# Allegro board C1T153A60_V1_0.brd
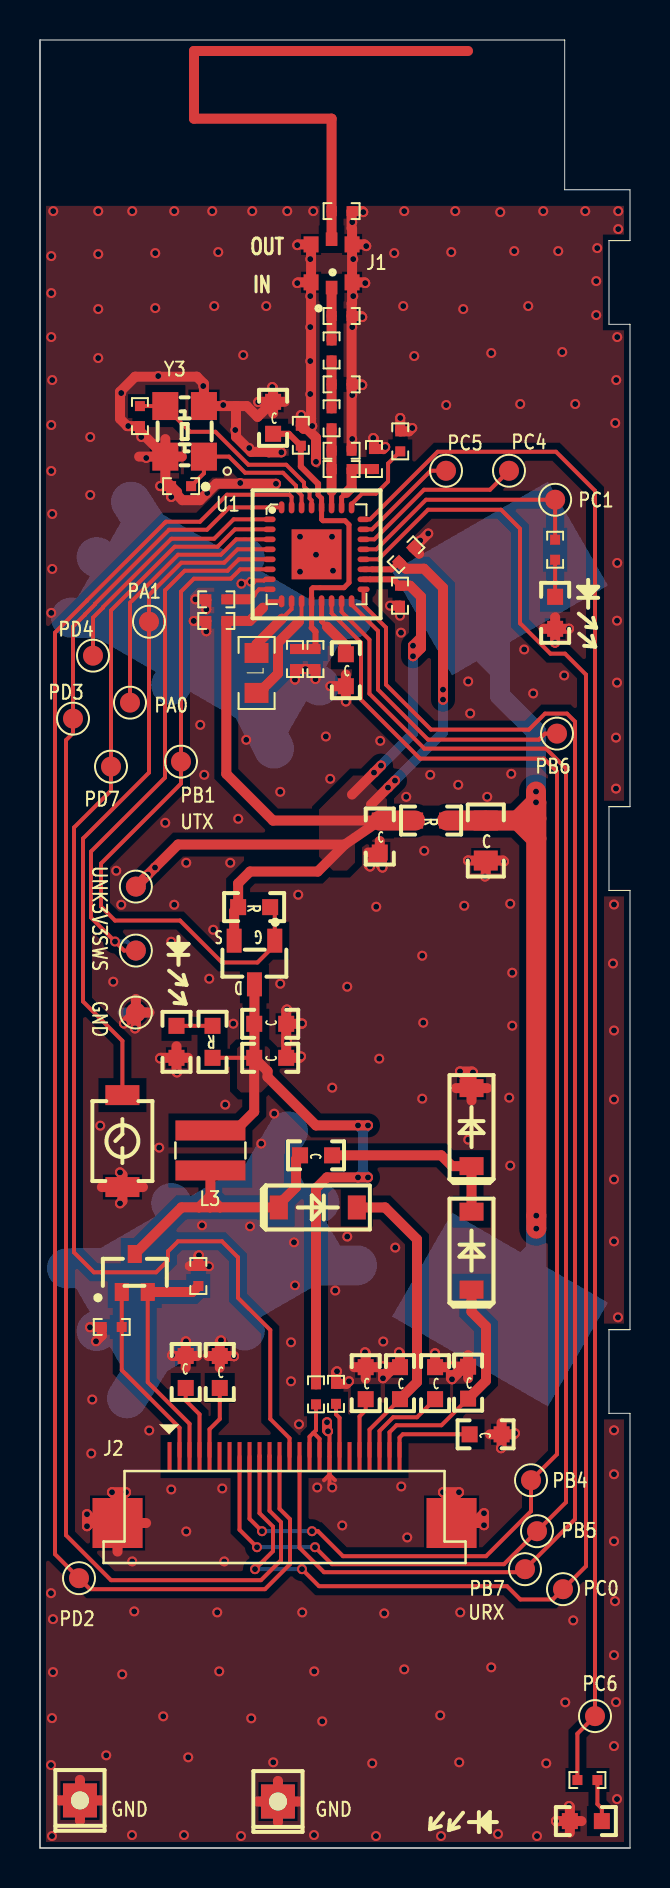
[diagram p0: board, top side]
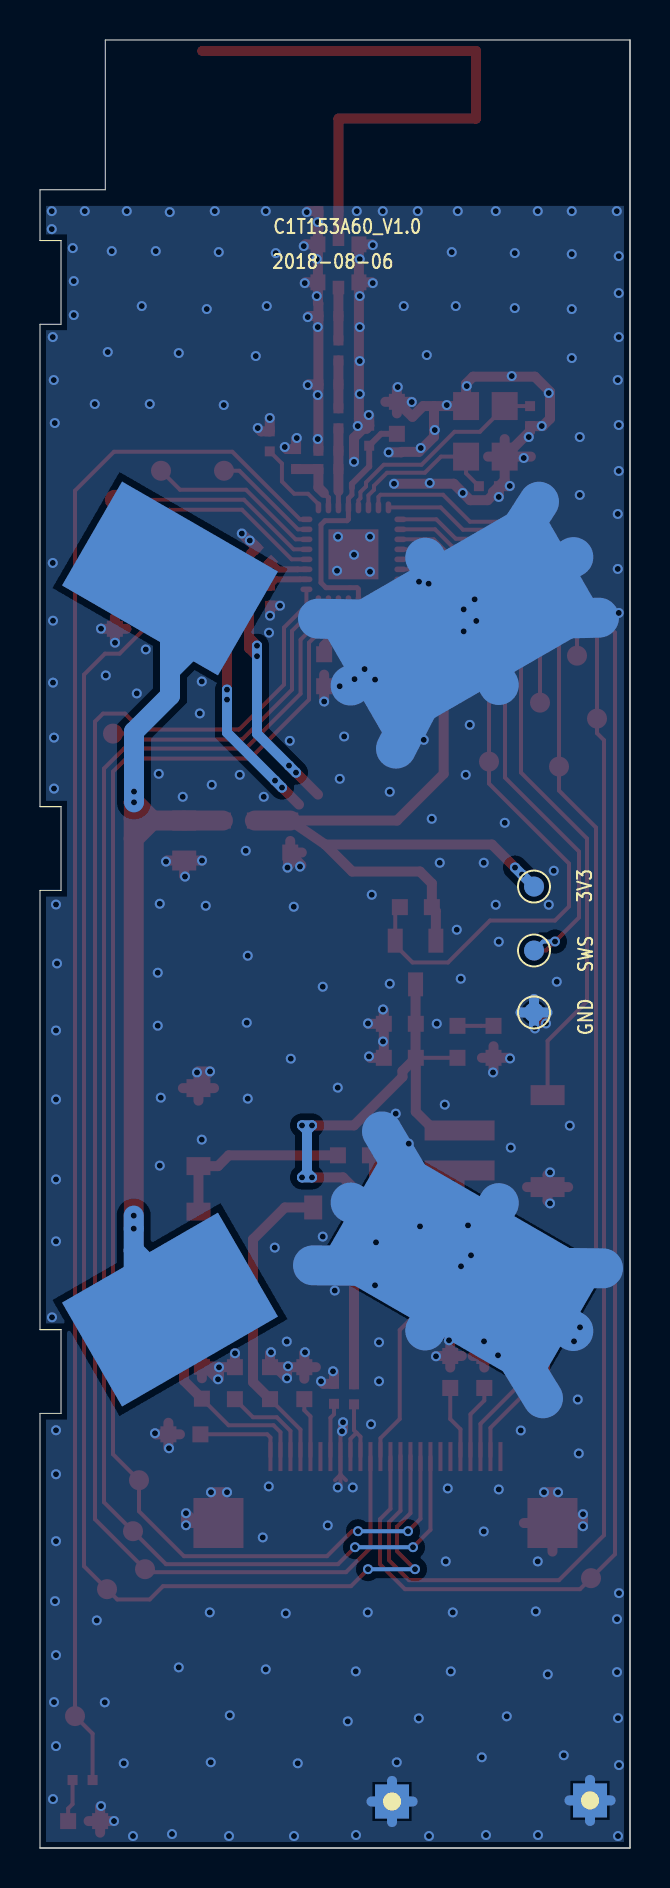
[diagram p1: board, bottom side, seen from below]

Outline 29.5 x 90.45 mm; copper layers: TOP, BOTTOM. Coordinates in mm from the lower left corner of the outline.
Outline path: 0,90.45 0,0 ; 0,90.45 26.23,90.45 26.23,82.96 29.5,82.96 29.5,80.42 ; 0,90.45 0,0 ; 0,0 29.5,0 ; 0,0 29.5,0 ; 29.5,0 29.5,21.74 28.45,21.74 28.45,25.93 ; 28.45,80.42 28.45,76.23 29.5,76.23 29.5,52.1 ; 28.45,80.42 29.5,80.42 ; 28.45,80.42 29.5,80.42 ; 28.45,52.1 28.45,47.9 29.5,47.9 29.5,25.93 ; 28.45,52.1 29.5,52.1 ; 28.45,52.1 29.5,52.1 ; 28.45,25.93 29.5,25.93 ; 28.45,25.93 29.5,25.93

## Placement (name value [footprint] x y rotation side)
BT3  3V  [BAT_P1]  8.4 29.08 90 bottom
C4  1.5pF  [0402]  15.08 73.22 0 top
C5  1.5pF  [0402]  15.08 76.64 0 top
C6  220pF  [0402]  14.58 71.52 90 top
C7  NC  [0402]  15.08 69.9 0 top
C8  1uF/25V  [0603C]  7.29 23.81 270 top
C9  1uF/25V  [0603C]  8.99 23.81 270 top
C10  1pF  [0402]  15.08 81.89 0 top
C13  1uF/25V  [0402]  14.8 22.72 270 top
C16  4.7uF/50V  [0603C]  13.8 34.65 180 top
C17  1uF/25V  [0603C]  19.75 23.25 270 top
C18  1uF/25V  [0603C]  16.28 23.25 270 top
C19  1uF/6V  [0603C]  22.28 20.7 180 top
C20  1uF/50V  [0603C]  18 23.26 270 top
C21  1uF/50V  [0603C]  21.4 23.28 270 top
C23  1uF  [0603C]  11.51 39.53 0 top
C24  10uF  [0603C]  11.51 41.23 0 top
C27  10uF  [0603C]  16.99 50.6 270 top
C28  10uF  [0805C]  22.29 50.4 270 top
C30  1uF  [0402]  18 62.65 270 top
C31  1uF  [0402]  8.82 61.39 180 top
C32  1uF  [0402]  8.82 62.47 0 top
C33  0.1uF  [0402]  13.77 59.48 270 top
C34  1uF  [0402]  18.01 70.37 90 top
C35  1uF  [0402]  12.75 59.48 270 top
C36  NC  [0402]  5 71.63 90 top
C37  NC  [0402]  7.05 68.13 0 top
C39  1uF  [0402]  18.3 64.7 45 top
C41  1uF  [0603C]  15.29 58.92 270 top
C42  18pF  [0402]  16.7 69.49 270 top
C43  0.1uF  [0402]  13.04 70.65 270 top
C44  2.2uF  [0603C]  11.65 71.55 270 top
D1  MBR0530  [SOD-123]  21.58 36.06 270 top
D2  MBR0530  [SOD-123]  13.89 32.04 180 top
D3  MBR0530  [SOD-123]  21.58 29.88 270 top
D4  Blue  [0603-LED]  6.82 40.33 270 top
D5  Green  [0603-LED]  27.29 1.35 180 top
D6  Red  [0603-LED]  25.76 61.79 270 top
GND  TP  [TP100]  4.79 41.8 90 top
J1  MM8130  [MM8130-2600]  14.58 79.27 180 top
J2  24FLZ-SM2-GD-TB  [FPC_24PIN]  12.23 19.58 0 top
J9  NC  [HDR254F-1X1X850]  2 2.38 90 top
J10  NC  [HDR254F-1X1X850]  11.9 2.33 90 top
L1  3nH  [0402]  14.58 74.92 90 top
L3  CD32-10UH  [CD32]  8.52 34.9 0 top
L5  1.3nH  [0402]  15.08 68.98 0 top
L6  47uH  [0805L]  10.83 58.78 90 top
PA0  TP  [TP100]  4.5 57.3 0 top
PA1  TP  [TP100]  5.45 61.35 0 top
PB1  TP  [TP100]  7.05 54.35 0 top
PB4  TP  [TP100]  24.55 18.4 0 top
PB5  TP  [TP100]  24.85 15.85 0 top
PB6  TP  [TP100]  25.85 55.75 0 top
PB7  TP  [TP100]  24.25 13.95 0 top
PC0  TP  [TP100]  26.15 12.95 0 top
PC1  TP  [TP100]  25.76 67.45 0 top
PC4  TP  [TP100]  23.45 68.9 0 top
PC5  TP  [TP100]  20.3 68.9 0 top
PC6  TP  [TP100]  27.75 6.6 0 top
PD2  TP  [TP100]  1.95 13.5 0 top
PD3  TP  [TP100]  1.65 56.5 0 top
PD4  TP  [TP100]  2.65 59.65 0 top
PD7  TP  [TP100]  3.55 54.1 0 top
Q1  SI1308EDL  [SOT-323]  4.74 28.77 0 top
Q2  PMOS_SI2301  [MOS_SOT-23]  10.72 44.3 180 top
R1  0.47R  [0402]  7.92 28.62 90 top
R2  1M  [0402]  3.59 26.07 180 top
R4  10R  [0402]  13.8 22.7 270 top
R6  1M  [0603R]  10.71 47.07 180 top
R7  3.3K  [0603R]  8.63 40.33 90 top
R10  2  [0603R]  19.55 51.4 180 top
R11  750R  [0402]  25.76 64.95 270 top
R12  750R  [0402]  27.37 3.4 0 top
SW1  BUT1  [BUTSMD2PX4_00Y3_00_NH]  4.12 35.37 0 top
SWS  TP  [TP100]  4.79 44.9 90 top
TP8  TP  [TP100]  4.8 48.1 180 bottom
TP9  TP  [TP100]  4.8 44.9 180 bottom
TP10  TP  [TP100]  4.8 41.8 180 bottom
U1  TLSR8359F512ET32  [QFN_5X5_32PIN_0P5_2P50X2P50]  13.83 64.72 0 top
UNK3V3  TP  [TP100]  4.79 48.1 90 top
Y3  24MHz-12pF-+/-20ppm  [OSCCC250X320X110]  7.23 70.87 180 top

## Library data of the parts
BT3 = SW_SL_DPDT_2
C4-C7 C10 = C1005_NC
C8 C9 C23 C24 = C1608X5R1C105M
C13 C16-C21 C36 C37 C41 C44 = C1608_NC
C27 C28 = C1608X5R0J106M
C30 = C1005X5R1C105K_1
C31 C33 C35 C42 C43 = C1005X5R1C105K_0
C32 C34 = C1005X5R1C105K
C39 = C1005X5R1C105K_3
D1-D3 = Diode_CDBW0520L-G
D4 = 0603D_Red
D5 D6 = 0603D_Green
GND PA0 PA1 PB1 PB4-PB7 PC0 PC1 PC4-PC6 PD2-PD4 PD7 SWS TP8-TP10 UNK3V3 = TestPad100
J1 = MM8130_1
J2 = CON_2.54mm_1x24
J9 J10 = CON1: Tolerance: RichardLC; User Part Number: pn
L1 = MLK1005S2N2ST
L3 = MLK1608S4N7ST
L5 L6 = IND_0
Q1 = NMOS_SI2302
Q2 = PMOS_SI2301
R1 R2 R4 = RS0402K000JT
R6 = RS0402K105JT
R7 = RS0402K332JT
R10 = RS0603K020JT
R11 R12 = RS0402K102JT
SW1 = SW PUSHBUTTON-SPST/SM
U1 = TLSR8359F512ET32
Y3 = CRYSTAL4/SM_0: Tolerance: RichardLC

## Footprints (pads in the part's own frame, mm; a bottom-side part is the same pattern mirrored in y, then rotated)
0402
  rect 0.5x0.5 smd: 1(-0.5,0) 2(0.5,0)
0603-LED
  rect 0.8x0.8 smd: A(-0.8,0) C(0.8,0)
0603C
  rect 0.8x0.8 smd: 1(-0.8,0) 2(0.8,0)
0603R
  rect 0.8x0.8 smd: 1(-0.8,0) 2(0.8,0)
0805C
  rect 1x1.2 smd: 1(-1,0) 2(1,0)
0805L
  rect 1x1.2 smd: 1(-1,0) 2(1,0)
BAT_P1
  rect 7x12.5 smd rot 150: 1(32.29,0)
  rect 6x9 smd rot 30: 2(34.434,14.6)
  rect 7x12.5 smd rot 30: 3(0,0)
  rect 6x9 smd rot 150: 4(-2.142,14.6)
BUTSMD2PX4_00Y3_00_NH
  rect 1.7x1 smd: 1(0,2.3) 2(0,-2.3)
CD32
  rect 3.5x1 smd: 1(0,1) 2(0,-1)
FPC_24PIN
  rect 0.2x1.45 smd: 1(-5.75,0) 2(-5.25,0) 3(-4.75,0) 4(-4.25,0) 5(-3.75,0) 6(-3.25,0) 7(-2.75,0) 8(-2.25,0) 9(-1.75,0) 10(-1.25,0) 11(-0.75,0) 12(-0.25,0) 13(0.25,0) 14(0.75,0) 15(1.25,0) 16(1.75,0) 17(2.25,0) 18(2.75,0) 19(3.25,0) 20(3.75,0) 21(4.25,0) 22(4.75,0) 23(5.25,0) 24(5.75,0)
  rect 2.5x2.5 smd: 25(-8.35,-3.325) 26(8.35,-3.325)
HDR254F-1X1X850
  rect 1.699x1.699 hole 0.899: 1(0,0)
MM8130-2600
  rect 0.58x0.68 smd: 1(0,1.21) 2(0,-1.21)
  rect 0.75x0.8 smd: 3(-1.025,0.95) 4(1.025,0.95) 5(-1.025,-0.95) 6(1.025,-0.95)
MOS_SOT-23
  rect 0.749x1.199 smd: 1(-1.016,-1.092) 2(1.016,-1.092) 3(0,1.092)
OSCCC250X320X110
  rect 1.3x1.399 smd: 1(-0.965,1.265) 2(-0.965,-1.265) 3(0.965,-1.265) 4(0.965,1.265)
QFN_5X5_32PIN_0P5_2P50X2P50
  oval 0.6x0.28 smd: 1(-2.35,1.75) 2(-2.35,1.25) 3(-2.35,0.75) 4(-2.35,0.25) 5(-2.35,-0.25) 6(-2.35,-0.75) 7(-2.35,-1.25) 8(-2.35,-1.75) 17(2.35,-1.75) 18(2.35,-1.25) 19(2.35,-0.75) 20(2.35,-0.25) 21(2.35,0.25) 22(2.35,0.75) 23(2.35,1.25) 24(2.35,1.75)
  oval 0.28x0.6 smd: 9(-1.75,-2.35) 10(-1.25,-2.35) 11(-0.75,-2.35) 12(-0.25,-2.35) 13(0.25,-2.35) 14(0.75,-2.35) 15(1.25,-2.35) 16(1.75,-2.35) 25(1.75,2.35) 26(1.25,2.35) 27(0.75,2.35) 28(0.25,2.35) 29(-0.25,2.35) 30(-0.75,2.35) 31(-1.25,2.35) 32(-1.75,2.35)
  rect 2.5x2.5 smd: 33(0,0)
SOD-123
  rect 0.899x1.199 smd: A(1.951,0) C(-1.951,0)
SOT-323
  rect 0.701x0.899 smd: 1(-0.65,-0.95) 2(0.65,-0.95) 3(0,0.95)
TP100
  round 1.001 smd: 1(0,0)

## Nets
3V3_EPD: C23.1 C24.1 L3.1 Q2.3(D) R4.1 R7.1
GND: BT3.1 BT3.3 C4.2 C5.2 C7.2 C8.1 C9.1 C10.2 C13.1 C17.1 C18.1 C19.1 C20.1 C21.1 C23.2 C24.2 C27.2 C28.2 C30.2 C31.2 C32.1 C33.2 C34.2 C35.2 C36.1 C37.1 C39.2 C41.2 C42.1 C43.1 C44.1 D1.C D4.C(CATHODE) D5.C(CATHODE) D6.C(CATHODE) GND.1(TP) J1.3 J1.4 J1.5 J1.6 J2.17(VSS) J2.25(GND1) J2.26(GND2) J9.1 J10.1 R1.2 R2.2 SW1.2 TP10.1(TP) U1.7(DVSS) U1.33(GND) Y3.2 Y3.4
TL_1.2V: C33.1 C35.1 C43.2 C44.2 U1.12(VDD1V2) U1.28(AVDD1V2)
TL_3V3: C27.1 C30.1 C31.1 C39.1 Q2.2(S) R6.2 R10.2 TP8.1(TP) U1.9(VDD_IO) U1.18(VDD3) U1.19(VDDIO_AMS) UNK3V3.1
TL_ANT: C6.1 C7.1 L5.1 U1.27(ANT)
TL_BS1: J2.8(BS1) PB5.1(TP) U1.15(P5/B[5])
TL_BUSY: J2.9(BUSY) PB4.1(TP) U1.14(P4/B[4])
TL_CK: J2.13(D0) PD7.1(TP) U1.2(CK/D[7])
TL_CS: J2.12(CS) PD2.1(TP) U1.31(CN/P3/D[2])
TL_D/C: J2.11(D/C) PD3.1(TP) U1.32(P1N/D[3])
TL_DO: J2.14(D1) PB7.1(TP) U1.17(DO/URX/B[7])
TL_GDR: J2.2(GDR) Q1.1(G) R2.1
TL_PA0: PA0.1(TP) U1.3(P0N/URX/A[0])
TL_PA1: PA1.1(TP) SW1.1 U1.4(A[1])
TL_PB1: PB1.1(TP) Q2.1(G) R6.1 U1.6(P4/UTX/ATSEL2/B[1])
TL_PB6: PB6.1(TP) U1.16(DI/URTS/B[6])
TL_PC1: PC1.1(TP) R11.1 U1.21(I2C_SCK/P1N/P0/PGAN0/C[1])
TL_PC4: PC4.1(TP) U1.22(P2/UCTS/P0N/C[4])
TL_PC5: PC5.1(TP) U1.23(P3N/URX/ATSEL0/C[5])
TL_PC6: PC6.1(TP) R12.1 U1.24(CYC2LNA/ATSEL1/P4N/C[6])
TL_PD4: PD4.1(TP) U1.1(SWM/P2N/D[4])
TL_RES: J2.10(RES) PC0.1(TP) U1.20(I2C_SDA/P4N/URTS/PGAP0/C[0])
TL_RESE: J2.3(RESE) Q1.2(S) R1.1
TL_SWS: SWS.1(TP) TP9.1(TP) U1.5(SWS/URTS/A[7])
TL_XC1: C36.2 U1.29(XC1) Y3.3
TL_XC2: C37.2 U1.30(XC2) Y3.1
VCOM: C19.2 J2.24(VCOM)
VGH: C20.2 D2.C J2.21(PREVGH)
N14875219: C5.1 J1.1 L1.2
N14875301: C4.1 C6.2 L1.1
N14928293: C10.1 J1.2
N14941163: C32.2 U1.8(VDD1V)
N14941231: L6.1 U1.11(VDCDC)
N14941235: L6.2 U1.10(VDCDC_SW)
N14941343: C41.1 U1.13(VDD_F)
N14941393: C34.1 U1.25(RESETB)
N14941421: C42.2 L5.2 U1.26(VANT)
N14943903: C13.2 J2.18(VDD)
N14944011: J2.15(VDDIO) J2.16(VCI) R4.2
N14944019: C8.2 J2.4(VGL)
N14944031: C9.2 J2.5(VGH)
N14944091: C21.2 D3.A J2.23(PREVGL)
N14944123: C17.2 J2.22(VSL)
N14944143: C18.2 J2.20(VSH)
N14944227: C16.2 D2.A L3.2 Q1.3(D)
N14944235: C16.1 D1.A D3.C
N14952885: BT3.2 BT3.4 C28.1 R10.1
N14956435: D4.A(ANODE) R7.2
N148761731: D6.A(ANODE) R11.2
N148761931: D5.A(ANODE) R12.2

Pads without a net: J2 1 6 7 19

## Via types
v1: diameter 0.5, hole 0.3, TOP to BOTTOM, 323 vias

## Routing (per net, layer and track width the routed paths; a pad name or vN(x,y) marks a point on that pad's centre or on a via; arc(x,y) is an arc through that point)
3V3_EPD: length 35.5
  TOP w0.2: C23.1 R7.1
  TOP w0.5: 10.72,41.25 10.72,43.21 ; 10.72,41.25 C24.1 ; 10.72,41.25 10.72,39.54 C23.1 ; R4.1 13.8,33 14.35,33.55 v1(15.9,33.55) v1(16.4,33.55) ; C23.1 10.71,36.83 9.77,35.9 L3.1 ; C23.1 11.38,38.86 11.38,38.57 13.8,36.15 v1(15.9,36.15) v1(16.4,36.15)
  BOTTOM w0.5: 16.15,35.9 v1(15.9,36.15) v1(16.4,36.15) 16.15,35.9 ; 16.15,35.9 16.15,33.8 ; 16.15,33.8 v1(15.9,33.55) v1(16.4,33.55) 16.15,33.8
GND: length 264
  TOP w0.2: U1.7 11.26,63.47 11.2,63.41 10.61,63.41 v1(10.55,63.35) 10.17,63.35 v1(10.07,63.25) ; 14.48,18.68 14.2,18.4 ; 14.48,18.68 14.48,18.67 ; 14.48,18.68 J2.17 14.48,20.77 v1(14.4,20.85) ; 14.75,18.4 14.48,18.67 ; 14.48,18.67 14.48,18.17 v1(14.61,18.04) ; 17.1,49.69 C27.2
  TOP w0.5: C18.1 16.28,24.77 v1(16.25,24.8) ; C18.1 15.71,24.06 ; C18.1 17.06,24.06 v1(17.1,24.1) 17.14,24.06 ; C18.1 16.28,23.48 ; 9.8,72.14 Y3.2 8.2,73.25 7.84,73.61 4.76,73.61 4,72.85 4,71.5 4.35,71.15 4.35,71.15 4.37,71.13 C36.1 5,70.88 Y3.4 ; 9.8,72.14 9.8,70.6 10.56,69.84 11.42,69.84 11.44,69.82 v1(12.07,69.82) ; 9.8,72.14 10.34,72.14 10.88,71.6 C44.1 ; D5.C 27.07,1.35 ; D5.C 26.49,0.77 ; D5.C 26.49,2.06 v1(26.45,2.1) ; D5.C 25.8,1.35 v1(25.8,1.35) ; v1(13.06,71.69) 13.04,71.67 C43.1 ; C8.1 7.86,24.61 ; C8.1 7.29,24.04 ; C8.1 7.29,25.33 v1(7.3,25.35) ; C8.1 6.63,24.61 v1(6.6,24.65) ; v1(16.26,78.29) 16.23,78.32 J1.3 ; C4.2 16.08,73.22 v1(16.11,73.19) ; C4.2 C7.2 ; C4.2 C5.2 ; v1(6.01,68.14) 6.02,68.13 C37.1 ; v1(12.86,80.19) 12.9,80.22 J1.6 J1.4 ; C28.2 22.29,48.64 v1(22.25,48.6) ; C28.2 21.4,49.4 v1(21.4,49.4) ; C28.2 23.15,49.4 v1(23.2,49.35) ; Y3.4 6.27,68.41 C37.1 ; Y3.4 4.96,69.61 ; Y3.4 6.27,70.48 ; Y3.4 7.1,69.61 ; v1(7.77,62.47) C32.1 v1(8.32,61.96) ; v1(4,33.8) 4.12,33.68 SW1.2 ; v1(9.05,25.4) 8.99,25.34 C9.1 ; C44.1 10.92,72.35 v1(10.91,72.34) ; C44.1 11.65,73.04 v1(11.61,73.09) ; C44.1 12.23,72.35 ; C44.1 11.65,71.77 ; v1(25.75,60.3) 25.76,60.31 D6.C ; v1(13.61,71.14) 13.55,71.2 13.55,71.52 ; v1(12.86,78.29) 12.9,78.32 J1.4 ; 0.97,2.38 J9.1 ; J9.1 2,1.35 ; J9.1 3.03,2.38 ; J9.1 2,3.41 ; 21.71,16.26 22.09,16.26 v1(22.2,16.15) v1(22.2,16.75) 21.71,16.26 ; 21.71,16.26 J2.26 20.58,17.37 ; 10.87,2.33 J10.1 ; J10.1 12.93,2.33 ; J10.1 11.9,1.3 ; J10.1 11.9,3.36 ; C21.1 21.4,24.66 ; C21.1 21.4,23.5 ; C21.1 21.23,24.08 ; v1(6.56,67.59) 6.55,67.6 C37.1 ; 21.58,38.27 v1(21,38.85) 21.6,38.85 v1(21.65,38.8) 21.58,38.73 21.58,38.27 ; 21.58,38.27 D1.C ; 2.79,16.26 2.51,16.26 v1(2.35,16.1) v1(2.35,16.7) 2.79,16.26 ; 2.79,16.26 3.88,16.26 ; C24.2 12.31,40.39 v1(12.35,40.35) 12.31,40.31 C23.2 12.98,39.53 v1(13.05,39.6) ; C24.2 13.08,41.23 v1(13.1,41.25) ; C24.2 12.31,41.91 v1(12.35,41.95) ; 17.71,24.06 C20.1 18,24.75 v1(17.95,24.8) ; 17.71,24.06 17.14,24.06 ; 17.71,24.06 v1(17.15,23.5) 17.15,24.05 17.14,24.06 ; R1.2 8.35,29.12 ; R1.2 7.49,29.12 ; R1.2 7.92,29.62 v1(7.95,29.65) ; J1.3 J1.5 ; J1.3 15.6,77.29 15.58,77.27 C5.2 ; v1(18.61,71.04) 18.44,70.87 C34.2 v1(18.01,71.54) ; 20.58,17.37 v1(20.15,17.8) v1(20.95,17.8) 20.58,17.43 20.58,17.37 ; v1(16.66,70.54) 16.7,70.5 C42.1 17.16,69.99 v1(17.26,70.09) ; C43.1 13.55,71.52 ; C43.1 13.18,71 13.35,71 13.8,70.55 v1(13.8,69.35) ; 13.55,71.52 J1.4 ; v1(20.55,24.05) 20.58,24.08 21.23,24.08 ; v1(20.55,24.05) 20.55,23.5 v1(20.6,23.45) 21.23,24.08 ; v1(20.55,24.05) 20.55,24.05 C17.1 19.75,24.74 v1(19.75,24.75) ; C9.1 9.68,24.61 v1(9.7,24.6) ; C9.1 8.99,24.04 ; C9.1 8.41,24.61 ; C19.1 23.08,20.03 v1(23.05,20) ; C19.1 23.7,20.7 v1(23.75,20.75) ; C19.1 23.08,21.27 ; C19.1 22.5,20.7 ; 3.88,14.83 3.88,16.26 ; 3.88,16.26 3.88,17.38 ; 3.88,16.26 5.3,16.26 ; v1(4.75,41) 4.79,41.04 GND.1 ; D4.C 7.4,39.53 ; D4.C 6.82,38.83 v1(6.85,38.8) ; D4.C 6.03,39.53 v1(6,39.5) ; D4.C 6.82,40.11 ; C41.2 v1(14.52,58.12) ; C41.2 v1(15.29,57.36) ; C41.2 15.29,58.7 ; J1.5 15.6,81 15.58,81.03 C10.2 16.11,81.89 v1(16.16,81.84) ; J1.5 16.23,80.22 v1(16.31,80.14) ; D6.C 25.76,61.57 ; D6.C 26.44,60.99 v1(26.45,61) ; D6.C 25.18,60.99 ; C27.2 16.99,50.38 ; C27.2 17.05,49.8 17.1,49.75 17.1,49.07 v1(17.12,49.05) ; C27.2 16.99,49.22 ; C27.2 16.44,49.16 v1(16.5,49.1) ; C27.2 16.41,49.8 ; C39.2 18.96,64.75 ; C39.2 18.96,65.36 ; C39.2 18.7,65.05 v1(19.41,65.76) ; v1(4.2,41.25) 4.75,41.8 GND.1 ; GND.1 5.47,41.8 ; GND.1 4.79,42.47 ; 21.58,37.39 D1.C ; D1.C 20.8,38.02 ; D1.C 22.35,38.02 ; v1(14.4,20.85) 14.35,20.9 v1(14.35,21.3) ; v1(2.8,25.35) 3.09,25.64 R2.2 2.52,26.07 v1(2.5,26.05) ; C37.1 6.85,67.83 6.85,67.69 7.12,67.43 7.99,67.43 8.81,68.25 v1(11.8,68.25) ; v1(14.85,23.85) 14.8,23.8 C13.1 15.32,23.22 v1(15.45,23.35) ; v1(13.77,58.48) C33.2 v1(13.27,58.98) C35.2 v1(12.75,58.45) ; C5.2 16.06,76.64 v1(16.11,76.59) ; 17.57,62.15 C30.2 18,61.72 ; 3.09,33.07 SW1.2 ; SW1.2 5.15,33.07 ; SW1.2 4.12,32.37 v1(4,32.25) ; 3.88,17.38 v1(4.3,17.8) v1(3.6,17.8) 3.88,17.52 3.88,17.38 ; v1(8.32,60.86) C31.2 v1(7.69,61.39)
  BOTTOM w0.5: 4.12,41.8 TP10.1 ; TP10.1 4.8,42.48 ; TP10.1 4.8,41.12 ; TP10.1 5.48,41.8 ; J9.1 2,3.41 ; J9.1 3.03,2.38 ; J9.1 2,1.35 ; J9.1 0.97,2.38 ; J10.1 12.93,2.33 ; J10.1 11.9,3.36 ; J10.1 11.9,1.3 ; J10.1 10.87,2.33
  BOTTOM w2: BT3.1 15.6,61.5 ; BT3.1 13.97,58.15 ; BT3.1 2.83,64.58 ; BT3.1 1.55,61.55 ; BT3.1 10.24,64.55 ; BT3.1 11.7,55 ; BT3.1 6.56,58.18 ; BT3.1 4.55,67.35 ; BT3.3 10.24,25.89 ; BT3.3 4.35,22.5 ; BT3.3 12.4,35.85 ; BT3.3 1.35,29 ; BT3.3 2.83,25.86 ; BT3.3 13.97,32.29 ; BT3.3 6.56,32.26 ; BT3.3 15.85,29.15
  vias: v1(0.56,79.64) v1(0.56,77.79) v1(0.56,75.59) v1(0.61,73.44) v1(0.56,71.19) v1(0.56,68.89) v1(0.61,66.74) v1(0.61,63.99) v1(0.56,61.79) v1(0.55,12.75) v1(0.6,6.5) v1(0.55,4.15) v1(0.6,0.6) v1(0.66,81.89) v1(0.65,11.45) v1(0.65,8.8) v1(2.51,70.59) v1(2.51,67.69) v1(2.61,22.44) v1(2.56,19.74) v1(2.91,81.89) v1(2.91,79.74) v1(2.91,76.99) v1(2.91,74.54) v1(3.01,36.14) v1(3.31,4.64) v1(3.66,43.34) v1(3.81,48.89) v1(4.06,72.79) v1(4.06,47.19) v1(4.11,8.69) v1(4.41,71.14) v1(4.61,81.89) v1(4.61,14.34) v1(4.6,0.65) v1(4.71,11.84) v1(5.06,70.59) v1(5.31,69.54) v1(5.46,20.89) v1(5.76,79.79) v1(5.76,77.04) v1(5.91,73.64) v1(5.96,35.04) v1(6.16,6.59) v1(6.26,51.29) v1(6.56,45.34) v1(6.56,17.94) v1(6.71,81.89) v1(6.71,47.19) v1(7.2,0.65) v1(7.31,49.29) v1(7.31,15.84) v1(7.41,4.54) v1(8.01,56.19) v1(8.1,31.15) v1(8.16,73.14) v1(8.21,53.69) v1(8.36,67.79) v1(8.45,29.1) v1(8.46,43.49) v1(8.61,81.89) v1(8.71,77.14) v1(8.66,45.94) v1(8.91,79.84) v1(8.86,11.79) v1(8.96,8.84) v1(9.11,17.99) v1(9.16,72.19) v1(9.21,14.34) v1(9.26,37.19) v1(9.51,49.29) v1(9.66,41.24) v1(9.76,70.94) v1(9.91,51.49) v1(10.01,68.29) v1(10.05,0.6) v1(10.16,74.69) v1(10.31,55.44) v1(10.46,70.04) v1(10.5,31.1) v1(10.61,81.89) v1(10.56,6.49) v1(11.06,35.24) v1(11.31,77.14) v1(11.71,36.74) v1(11.66,4.29) v1(12.01,52.84) v1(12.01,43.24) v1(12.36,81.89) v1(12.55,25.3) v1(12.55,23.35) v1(12.7,30.3) v1(12.75,28.15) v1(12.91,47.69) v1(12.95,21.2) v1(13,65.6) v1(13,63.85) v1(13.11,11.79) v1(13.51,79.49) v1(13.51,77.64) v1(13.51,76.09) v1(13.51,74.39) v1(13.51,72.74) v1(13.66,81.89) v1(13.71,8.84) v1(13.7,0.65) v1(13.8,64.7) v1(13.86,18.04) v1(14.11,6.34) v1(14.29,55.61) v1(14.51,53.49) v1(14.6,65.6) v1(14.61,38.04) v1(14.65,63.9) v1(14.76,27.89) v1(15.11,16.14) v1(15.36,43.09) v1(15.36,30.59) v1(15.61,81.34) v1(15.61,76.09) v1(15.61,72.69) v1(15.61,70.49) v1(15.66,79.49) v1(15.66,77.64) v1(16.61,4.24) v1(16.81,47.09) v1(16.8,0.6) v1(17.01,55.39) v1(16.96,39.49) v1(17.16,25.34) v1(17.21,11.74) v1(17.5,62.15) v1(17.71,79.79) v1(17.76,30.04) v1(18,61.65) v1(18.05,60.8) v1(18.06,18.09) v1(18.21,81.89) v1(18.16,77.14) v1(18.21,8.94) v1(18.31,52.59) v1(18.36,15.54) v1(18.71,74.64) v1(19.01,65.41) v1(19.11,44.64) v1(19.11,37.49) v1(19.21,49.89) v1(19.16,41.29) v1(19.51,53.69) v1(20.01,6.64) v1(20.05,0.6) v1(20.31,72.19) v1(20.56,79.84) v1(20.76,81.89) v1(20.91,53.19) v1(21.01,11.79) v1(20.96,4.29) v1(21.16,76.99) v1(21.21,47.14) v1(21.41,58.36) v1(21.41,35.44) v1(21.51,56.76) v1(22.36,52.59) v1(22.56,74.79) v1(22.56,9.04) v1(22.9,0.7) v1(23.01,81.84) v1(23.51,47.24) v1(23.46,37.54) v1(23.51,34.14) v1(23.56,53.74) v1(23.61,43.79) v1(23.61,41.14) v1(23.71,79.89) v1(24.01,72.24) v1(24.21,59.96) v1(24.41,77.14) v1(24.66,57.76) v1(24.85,0.6) v1(25.16,81.89) v1(25.31,4.24) v1(25.91,79.89) v1(26.11,74.84) v1(26.21,58.66) v1(26.26,7.29) v1(26.66,11.39) v1(26.76,72.24) v1(27.26,81.89) v1(27.81,78.39) v1(27.81,76.69) v1(27.86,80.04) v1(28.65,44.25) v1(28.7,47.2) v1(28.7,40.9) v1(28.7,37.45) v1(28.7,33.45) v1(28.7,30.35) v1(28.7,20.9) v1(28.7,18.7) v1(28.7,15.35) v1(28.7,9.65) v1(28.7,5.1) v1(28.81,73.44) v1(28.76,71.29) v1(28.8,55.55) v1(28.8,53) v1(28.75,12.35) v1(28.8,7.3) v1(28.91,81.89) v1(28.91,80.99) v1(28.86,75.59) v1(28.86,64.29) v1(28.85,61.4) v1(28.85,58.3) v1(28.9,26.55) v1(28.85,2.45)
TL_1.2V: length 16.2
  TOP w0.25: 13.58,61.05 U1.12 13.58,62.98 13.65,63.05 14,63.05 15.2,63.05 15.45,63.3 15.45,66.2 15.25,66.4 14.15,66.4 14.08,66.47 U1.28 14.08,67.52 13.9,67.7 13.9,68.05
  TOP w0.3: C44.2 12.44,70.75 C43.2 13.04,69.11 13.9,68.25 13.9,68.05 ; 13.58,61.05 13.77,60.85 C33.1
  TOP w0.5: C35.1 C33.1
TL_3V3: length 79.8
  TOP w0.2: U1.9 11.47,62.37 11.15,62.05
  TOP w0.28: 16.5,63.47 16.18,63.47 ; 16.62,63.97 16.18,63.97
  TOP w0.3: 16.5,63.47 17.68,63.47 C30.1 ; 16.62,63.97 17.57,63.97 C39.1
  TOP w0.5: 19.05,60.55 19.05,60.02 v1(18.65,59.62) v1(18.65,60.15) 19.05,60.55 ; 19.05,60.55 19.05,62.6 18.5,63.15 C30.1 ; UNK3V3.1 4.8,48.1 v1(5.4,48.7) v1(5.75,49.05) 6.9,50.2 15.24,50.2 ; C39.1 18.29,64 19.2,64 20.15,63.05 v1(20.15,57.95) v1(20.15,57.45) ; 16.55,52.2 v1(17.4,53.05) v1(17.75,53.4) ; 15.24,50.2 13.89,48.85 10.5,48.85 9.91,48.26 R6.2 9.71,46.87 Q2.2 ; 15.24,50.2 C27.1 11.65,51.4 9.32,53.73 C31.1 10.49,61.39 11.15,62.05 ; 15.6,52.7 v1(16.7,53.8) v1(17.05,54.15)
  TOP w1: R10.2 C27.1
  BOTTOM w0.5: v1(16.7,53.8) v1(17.05,54.15) 18.65,55.75 v1(18.65,59.62) v1(18.65,60.15) ; v1(17.4,53.05) v1(17.75,53.4) 20.15,55.8 v1(20.15,57.45) v1(20.15,57.95) ; v1(5.75,49.05) v1(5.4,48.7) TP8.1
TL_ANT: length 4
  TOP w0.254: U1.27 14.58,67.88
  TOP w0.5: C6.1 C7.1 L5.1 14.58,67.88
TL_BS1: length 75.3
  TOP w0.2: J2.8 9.98,15.92 v1(10.85,15.05) ; U1.15 15.08,61.84 16.47,60.45 16.47,57.75 19.22,55 25.3,55 26.3,54 26.3,17.3 PB5.1 23.2,14.2 14.6,14.2 v1(13.75,15.05)
  BOTTOM w0.2: v1(10.85,15.05) v1(13.75,15.05)
TL_BUSY: length 73.3
  TOP w0.2: U1.14 14.58,61.77 16.05,60.3 16.05,57.45 19,54.5 25.2,54.5 25.85,53.85 25.85,19.7 PB4.1 24.55,16.85 22.3,14.6 15.15,14.6 13.9,15.85 v1(13.6,15.85) ; J2.9 10.48,16.47 v1(11.1,15.85)
  BOTTOM w0.2: v1(13.6,15.85) v1(11.1,15.85)
TL_CK: length 63.4
  TOP w0.2: U1.2 9.75,65.97 8.88,65.1 6.74,65.1 3.55,61.91 PD7.1 3.55,52.9 1.7,51.05 1.7,29.8 2.7,28.8 5.8,28.8 6.4,29.4 6.4,29.85 6.9,30.35 9.1,30.35 9.9,29.55 9.9,27.53 11.51,25.91 11.51,21.46 12.48,20.5 J2.13
TL_CS: length 80
  TOP w0.2: J2.12 11.98,16.97 12.5,16.45 12.5,14.2 11.25,12.95 2.5,12.95 PD2.1 0.75,14.7 0.75,60.8 2.35,62.4 2.35,62.41 6.24,66.3 6.25,66.3 6.3,66.35 8,66.35 9.35,67.7 12.47,67.7 12.58,67.59 U1.31
TL_D/C: length 76.1
  TOP w0.2: 11.48,19.65 J2.11 11.48,16.87 12.05,16.3 12.05,14.4 11.05,13.4 3.55,13.4 1.3,15.65 1.3,55.42 1.65,55.77 PD3.1 1.65,61.1 2.25,61.7 2.25,61.72 2.75,62.22 2.75,62.24 6.46,65.95 8.35,65.95 9.47,67.07 U1.32
TL_DO: length 76
  TOP w0.2: 16.18,62.97 16.18,62.17 17.3,61.05 17.3,58.2 19.55,55.95 24.45,55.95 25.25,56.75 26.35,56.75 26.75,56.35 26.75,16.45 PB7.1 24.1,13.8 14.2,13.8 12.98,15.02 J2.14
TL_GDR: length 9.4
  TOP w0.2: J2.2 6.98,21.02 4.09,23.91 R2.1 Q1.1
TL_PA0: length 13.3
  TOP w0.2: PA0.1 4.5,62.3 6.9,64.7 9.04,64.7 9.81,65.47 U1.3
TL_PA1: length 34.2
  TOP w0.2: SW1.1 4.12,40.38 2.15,42.35 2.15,50.5 5.45,53.8 PA1.1 5.45,62.68 7.07,64.3 9.21,64.3 9.88,64.97 U1.4
TL_PB1: length 34.5
  TOP w0.2: U1.6 10.01,63.97 9.54,63.5 7.7,63.5 7.05,62.85 PB1.1 7.05,53.25 3.05,49.25 3.05,47.1 3.75,46.4 7,46.4 9.1,44.3 10.87,44.3 11.74,45.17 Q2.1 11.74,46.84 R6.1
TL_PB6: length 15.1
  TOP w0.2: U1.16 15.58,62.21 16.9,60.89 16.9,57.95 19.4,55.45 24.95,55.45 25.25,55.75 PB6.1
TL_PC1: length 12.6
  TOP w0.2: R11.1 PC1.1 19.3,67.45 16.82,64.97 16.18,64.97
TL_PC4: length 8.7
  TOP w0.2: PC4.1 22.5,67.95 19.2,67.95 16.72,65.47 16.18,65.47
TL_PC5: length 5.3
  TOP w0.2: PC5.1 19.53,68.9 16.6,65.97 16.18,65.97
TL_PC6: length 78.6
  TOP w0.2: 16.18,66.47 16.5,66.47 19.88,69.85 25.8,69.85 27.75,67.9 PC6.1 26.87,5.72 R12.1
TL_PD4: length 12.8
  TOP w0.2: U1.1 9.68,66.47 8.71,65.5 6.57,65.5 3.15,62.08 3.15,62.05 2.65,61.55 PD4.1
TL_RES: length 87.2
  TOP w0.2: 10.98,19.65 J2.10 10.98,16.75 11.65,16.08 11.65,14.85 v1(10.75,13.95) ; 16.18,64.47 16.92,64.47 19.4,66.95 23.05,66.95 24,66 24,61.27 25.52,59.75 26.25,59.75 27.3,58.7 27.3,14.1 PC0.1 25.64,12.44 24.01,12.44 23.35,13.1 13.95,13.1 v1(13.1,13.95)
  BOTTOM w0.2: v1(10.75,13.95) v1(13.1,13.95)
TL_RESE: length 11.8
  TOP w0.2: J2.3 7.48,21.22 5.39,23.31 Q1.2
  TOP w0.5: Q1.2 7.62,27.82 R1.1
TL_SWS: length 27.9
  TOP w0.2: U1.5 9.94,64.47 9.37,63.9 7.23,63.9 6.25,62.91 6.25,61.68 6.25,53.55 2.55,49.85 2.55,46.55 v1(3.75,45.35) 4.2,44.9 SWS.1
  BOTTOM w0.2: TP9.1 4.35,45.35 v1(3.75,45.35)
TL_XC1: length 11.2
  TOP w0.2: U1.29 13.58,67.42 13.48,67.52 13.48,67.83 13.2,68.11 13.2,68.31 12.31,69.2 10.42,69.2 8.77,70.85 7.5,70.85 6.27,72.09 Y3.3 5,72.14 C36.2
TL_XC2: length 8.1
  TOP w0.2: C37.2 8.2,68.77 Y3.1 9.45,69.61 10.26,68.8 12.15,68.8 12.8,68.15 12.8,67.95 13.08,67.67 U1.30
VCOM: length 4.5
  TOP w0.2: J2.24 17.98,20.54 18.14,20.7 21.48,20.7 C19.2
VGH: length 15.5
  TOP w0.2: J2.21 16.48,20.93 C20.2
  TOP w0.5: C20.2 18.85,23.31 18.85,30.45 17.26,32.04 D2.C
N14875219: length 2.6
  TOP w0.5: J1.1 C5.1 L1.2
N14875301: length 2.4
  TOP w0.5: L1.1 C4.1 C6.2
N14928293: length 30
  TOP w0.5: J1.2 C10.1 14.58,86.51 7.7,86.51 7.7,89.9 21.4,89.9
N14941163: length 2.4
  TOP w0.2: 10.68,62.68 10.77,62.77 10.77,62.79 10.95,62.97 U1.8
  TOP w0.3: 10.68,62.68 10.47,62.47
  TOP w0.5: 10.47,62.47 C32.2
N14941231: length 5.6
  TOP w0.2: U1.11 13.08,61.48 12.95,61.35
  TOP w0.5: 12.95,61.35 11.9,60.3 11.9,58.76 10.93,57.78 L6.1
N14941235: length 3.3
  TOP w0.2: 12.1,61.5 12.58,61.98 U1.10
  TOP w0.5: 12.1,61.5 10.83,60.23 L6.2
N14941343: length 3.2
  TOP w0.25: 14.35,61.1 14.08,61.37 U1.13
  TOP w0.5: 14.35,61.1 15.29,60.16 C41.1
N14941393: length 4.2
  TOP w0.2: C34.1 17.4,69.26 17.4,68.36 16.79,67.75 16.1,67.75 15.58,67.23 U1.25
N14941421: length 3.2
  TOP w0.25: U1.26 15.08,67.56 15.31,67.79
  TOP w0.5: 15.31,67.79 15.58,68.06 L5.2 C42.2
N14943903: length 2.7
  TOP w0.2: C13.2 14.8,21.7 14.98,21.52 J2.18
N14944011: length 4.1
  TOP w0.2: 13.68,20.77 13.98,20.47 J2.16 ; 13.68,20.77 13.8,20.9 R4.2 ; 13.68,20.77 13.48,20.58 J2.15
N14944019: length 3.7
  TOP w0.2: C8.2 7.29,22.39 7.98,21.7 J2.4
N14944031: length 3.6
  TOP w0.2: C9.2 8.99,21.46 8.48,20.95 J2.5
N14944091: length 12
  TOP w0.2: J2.23 17.48,20.8 17.82,21.15 20.07,21.15 C21.2
  TOP w0.5: D3.A 21.58,26.82 22.3,26.1 22.3,23.38 C21.2
N14944123: length 4.7
  TOP w0.2: J2.22 16.98,20.87 17.66,21.55 18.85,21.55 C17.2
N14944143: length 3
  TOP w0.2: J2.20 15.98,21.59 16.28,21.9 C18.2
N14944227: length 14.6
  TOP w0.5: 7.95,32.05 7.07,32.05 Q1.3 ; 7.95,32.05 8.52,32.62 ; 7.95,32.05 8.5,32.05 ; 8.52,32.62 8.52,32.53 ; 8.52,32.62 L3.2 ; 8.52,32.53 8.52,32.07 8.5,32.05 ; 8.52,32.53 9,32.05 ; 8.5,32.05 9,32.05 ; 9,32.05 11.11,32.05 11.11,32.04 D2.A 11.94,32.19 12.8,33.06 12.8,34.45 C16.2
N14944235: length 9.5
  TOP w0.5: C16.1 20.06,34.65 20.6,34.11 D1.A D3.C
N14952885: length 52.4
  TOP w1: 23.91,51.4 23.91,51.43 v1(24.8,52.31) ; 23.91,51.4 24.81,50.5 ; 23.91,51.4 24.71,51.4 24.81,51.5 ; 23.91,51.4 C28.1 R10.1 ; 24.81,51.5 24.81,50.5 ; 24.81,51.5 24.81,52.3 v1(24.8,52.31) ; 24.81,50.5 v1(24.81,31.64) v1(24.81,30.99) ; v1(24.8,52.31) v1(24.8,52.85)
  BOTTOM w1: BT3.2 23,58.9 ; 23,58.9 23,57.65 24.8,55.85 v1(24.8,52.85) v1(24.8,52.31) ; 23,58.9 22,59.9 22,60.85 ; 24.81,29.9 v1(24.81,30.99) v1(24.81,31.64) ; 24.81,29.9 23,28.09 BT3.4 24.81,28.75 24.81,29.9
N14956435: length 1.8
  TOP w0.2: D4.A 7.45,41.13 R7.2
N148761731: length 1.9
  TOP w0.2: R11.2 D6.A
N148761931: length 2.1
  TOP w0.2: D5.A 28.09,1.97 27.87,2.2 R12.2

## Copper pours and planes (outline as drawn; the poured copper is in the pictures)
3V3_EPD on TOP: 9.95,40.1 11.35,40.1 11.5,39.95 11.5,38.25 11.05,37.8 10.05,37.8 9.85,38 9.85,40
GND on TOP: 0.3,0.3 0.3,82.15 29.2,82.15 29.2,80.72 28.15,80.72 28.15,75.93 29.2,75.93 29.2,52.4 28.15,52.4 28.15,47.6 29.2,47.6 29.2,26.23 28.15,26.23 28.15,21.44 29.2,21.44 29.2,0.3 ; 9 cut-outs
GND on BOTTOM: 0.3,0.3 0.3,82.15 29.2,82.15 29.2,80.72 28.15,80.72 28.15,75.93 29.2,75.93 29.2,52.4 28.15,52.4 28.15,47.6 29.2,47.6 29.2,26.23 28.15,26.23 28.15,21.44 29.2,21.44 29.2,0.3 ; 1 cut-out
TL_3V3 on TOP: 17.35,50.85 17.35,52.45 16.15,53.65 15.65,53.65 13.95,51.95 13.95,49.6 14.65,48.9 15.35,48.9 15.75,49.3 15.75,50.25 16.35,50.85

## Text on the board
Ref Des/Silkscreen Bottom: C1T153A60_V1.0 | 2018-08-06 | SWS | GND | 3V3
User.Comments: P5 | P6 | PWR | 2 | 10 | 1 | 9
Ref Des/Silkscreen Top: GND | UTX | URX
COMPVAL_TYPE_BOTTOM: FIGURE | SIZE | 0.3 | 0.8992 | DRILL CHART: TOP to BOTTOM | ALL UNITS ARE IN MILLIMETERS | PLATED | QTY | 323 | 2
